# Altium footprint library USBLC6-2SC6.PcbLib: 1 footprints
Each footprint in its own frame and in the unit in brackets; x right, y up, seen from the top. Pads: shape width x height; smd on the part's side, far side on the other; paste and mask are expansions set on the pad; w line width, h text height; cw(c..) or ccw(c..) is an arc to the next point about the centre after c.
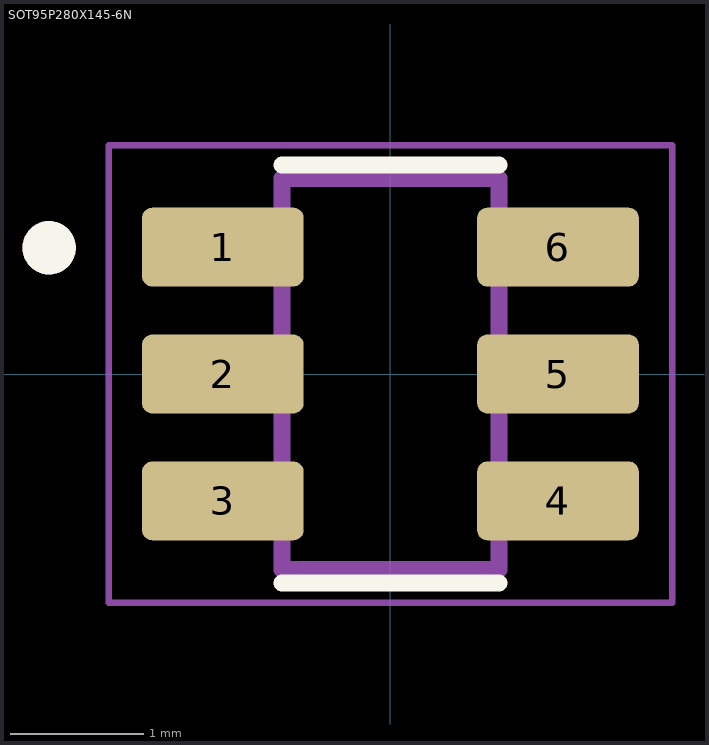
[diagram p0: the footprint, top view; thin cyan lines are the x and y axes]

## SOT95P280X145-6N [mm]
pads (6):
  rrect25% 1.21x0.59 smd: 1(-1.255,0.95) 2(-1.255,0) 3(-1.255,-0.95) 4(1.255,-0.95) 5(1.255,0) 6(1.255,0.95)
Top Overlay:
  circle w0.2: c-2.555,0.945 r0.1
  lines w0.127: -0.813,-1.565 0.813,-1.565 ; -0.813,1.565 0.813,1.565
Mechanical 13:
  circle w0.2: c-2.555,0.945 r0.1
  lines w0.127: -0.813,-1.462 -0.813,1.462 0.813,1.462 0.813,-1.462 -0.813,-1.462
Mechanical 15:
  lines w0.05: -2.11,-1.713 2.11,-1.713 2.11,1.713 -2.11,1.713 -2.11,-1.713
3D body "step_temp.STEP": height 0.4, standoff -1.05, extent -1.4,-1.462 1.4,1.462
